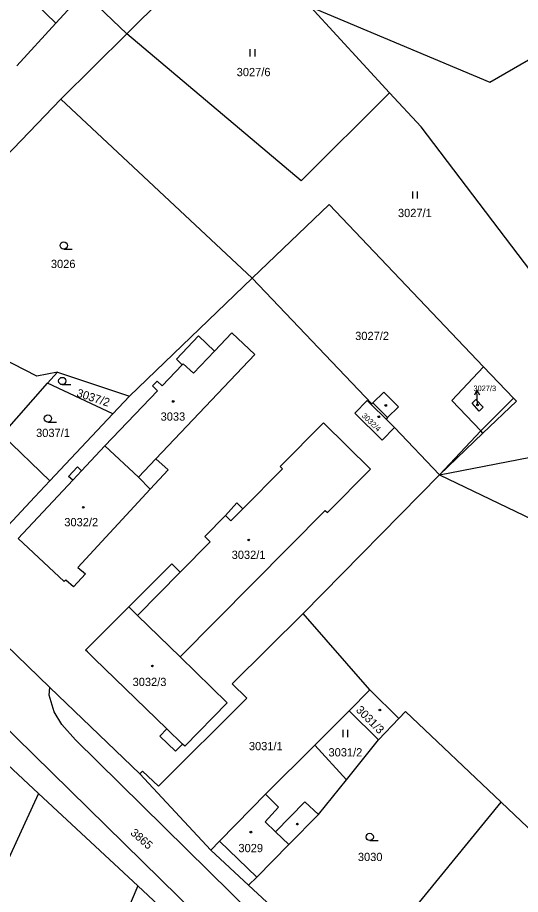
# Model space of a CAD drawing. Extents: x -527335 to -526256, y -1079142 to -1077809.
# Drawn here: x -526577.1 to -526473.7, y -1078894.6 to -1078714.2 of the extents above; entities that cross this region are included whole.
import ezdxf

# ---------------------------------------------------------------- set-up
doc = ezdxf.new("R2010")
doc.units = 0
for name, color, linetype in [('Vrstva 1', 7, 'Continuous'), ('Vrstva 2', 7, 'Continuous'), ('Vrstva 3', 7, 'Continuous'), ('Vrstva 4', 7, 'Continuous'), ('Vrstva 5', 7, 'Continuous'), ('Vrstva 7', 7, 'Continuous')]:
    doc.layers.add(name, color=color, linetype=linetype)

msp = doc.modelspace()

# ---------------------------------------------------------------- linework, layer by layer
at = {"layer": 'Vrstva 1'}
for p, q in [((-526554.68, -1078717.53), (-526539.54, -1078702.51)), ((-526516.89, -1078712.01), (-526500.66, -1078729.66)), ((-526577.27, -1078724.14), (-526569.24, -1078715.32)), ((-526568.24, -1078730.99), (-526554.68, -1078717.53)), ((-526602.93, -1078766.96), (-526568.24, -1078730.99)), ((-526528.93, -1078767.79), (-526568.24, -1078730.99)), ((-526554.11, -1078792.09), (-526528.93, -1078767.79)), ((-526528.93, -1078767.79), (-526504.29, -1078793.67)), ((-526571, -1078789.45), (-526568.95, -1078787.13)), ((-526568.95, -1078787.13), (-526554.11, -1078792.09)), ((-526580.33, -1078800.02), (-526571, -1078789.45)), ((-526557.53, -1078795.73), (-526571, -1078789.45)), ((-526554.11, -1078792.09), (-526557.53, -1078795.73)), ((-526570.48, -1078809.52), (-526557.53, -1078795.73)), ((-526499.66, -1078798.54), (-526490.41, -1078808.25)), ((-526570.48, -1078809.52), (-526580.33, -1078800.02)), ((-526481.45, -1078799.72), (-526490.41, -1078808.25)), ((-526490.41, -1078808.25), (-526446.22, -1078799.76)), ((-526573.56, -1078812.8), (-526570.48, -1078809.52)), ((-526518.39, -1078836.79), (-526490.41, -1078808.25)), ((-526490.41, -1078808.25), (-526410.53, -1078846.68)), ((-526504.69, -1078852.51), (-526518.39, -1078836.79)), ((-526572.83, -1078873.83), (-526599.63, -1078848.92)), ((-526508.94, -1078856.81), (-526504.69, -1078852.51)), ((-526504.69, -1078852.51), (-526498.72, -1078858.41)), ((-526508.94, -1078856.81), (-526516.02, -1078863.88)), ((-526502.9, -1078862.78), (-526508.94, -1078856.81)), ((-526498.72, -1078858.41), (-526502.9, -1078862.78)), ((-526509.51, -1078870.99), (-526502.9, -1078862.78)), ((-526516.02, -1078863.88), (-526526.14, -1078873.99)), ((-526509.51, -1078870.99), (-526516.02, -1078863.88)), ((-526552.02, -1078869.8), (-526537.38, -1078885.46)), ((-526515.27, -1078878.15), (-526509.51, -1078870.99)), ((-526552.41, -1078892.82), (-526572.83, -1078873.83)), ((-526508.07, -1078912.73), (-526477.68, -1078875.63)), ((-526477.68, -1078875.63), (-526463.23, -1078889.43)), ((-526537.38, -1078885.46), (-526529.63, -1078892.67)), ((-526552.41, -1078892.82), (-526555.43, -1078899.96)), ((-526534.91, -1078909.1), (-526552.41, -1078892.82)), ((-526529.63, -1078892.67), (-526508.07, -1078912.73))]:
    msp.add_line(p, q, dxfattribs=at)
for points in [[(-526569.24, -1078715.32), (-526590.17, -1078695.14), (-526598.14, -1078704.26)], [(-526554.68, -1078717.53), (-526563.51, -1078709.03), (-526569.24, -1078715.32)], [(-526516.89, -1078712.01), (-526480.01, -1078727.48), (-526459.29, -1078715.49)], [(-526500.66, -1078729.66), (-526518.84, -1078747.8), (-526554.68, -1078717.53)], [(-526446.22, -1078799.76), (-526494.18, -1078736.71), (-526500.66, -1078729.66)], [(-526528.93, -1078767.79), (-526513.06, -1078752.68), (-526481.31, -1078786.03)], [(-526559.18, -1078802.32), (-526548.37, -1078790.96), (-526549.41, -1078789.97), (-526548.43, -1078788.98), (-526547.41, -1078789.95), (-526543.29, -1078785.62), (-526544.48, -1078784.47), (-526539.92, -1078779.69), (-526536.66, -1078782.81), (-526533.1, -1078779.08), (-526528.38, -1078783.55), (-526548.71, -1078804.96)], [(-526568.95, -1078787.13), (-526573.17, -1078787.97), (-526583, -1078782.94)], [(-526481.45, -1078799.72), (-526481.91, -1078799.24), (-526487.82, -1078793.01), (-526481.31, -1078786.03)], [(-526481.31, -1078786.03), (-526475.18, -1078792.47), (-526474.54, -1078793.14), (-526481.45, -1078799.72)], [(-526504.29, -1078793.67), (-526504.13, -1078793.49), (-526501.86, -1078791.24), (-526498.83, -1078794.3), (-526501.07, -1078796.51), (-526501.37, -1078796.8), (-526499.64, -1078798.52), (-526499.66, -1078798.54)], [(-526499.66, -1078798.54), (-526502.17, -1078801.11), (-526507.83, -1078795.56), (-526505.29, -1078792.97), (-526504.44, -1078793.81), (-526504.29, -1078793.67)], [(-526548.71, -1078804.96), (-526546.18, -1078807.27), (-526549.87, -1078811.21), (-526564.78, -1078827.33), (-526563.18, -1078828.67), (-526565.67, -1078831.32), (-526567.24, -1078829.94), (-526567.55, -1078830.24), (-526577.02, -1078821.35), (-526565.81, -1078809.39), (-526566.65, -1078808.6), (-526564.81, -1078806.64), (-526563.97, -1078807.43), (-526559.18, -1078802.32)], [(-526548.71, -1078804.96), (-526552.31, -1078808.75), (-526559.18, -1078802.32)], [(-526592.15, -1078831.2), (-526590.73, -1078829.68), (-526583.18, -1078822.03), (-526580.48, -1078819.73), (-526580.05, -1078819.71), (-526573.56, -1078812.8)], [(-526592.15, -1078831.2), (-526581.94, -1078841.02), (-526570.51, -1078852.02), (-526552.02, -1078869.8)], [(-526534.07, -1078855.15), (-526542.75, -1078864.11), (-526543.21, -1078863.71), (-526544.66, -1078865.16), (-526547.92, -1078862.03), (-526546.45, -1078860.51), (-526561.4, -1078846.03), (-526562.78, -1078844.67), (-526563.17, -1078844.34), (-526559.27, -1078840.44), (-526554.28, -1078835.46), (-526552.5, -1078837.19), (-526543.73, -1078845.74), (-526534.07, -1078855.15)], [(-526518.39, -1078836.79), (-526533.02, -1078851.25), (-526529.98, -1078854.21), (-526548.16, -1078872.34), (-526551.44, -1078869.24), (-526552.02, -1078869.8)], [(-526477.68, -1078875.63), (-526497.36, -1078856.99), (-526498.72, -1078858.41)], [(-526572.83, -1078873.83), (-526575.65, -1078879.95), (-526588.32, -1078907.48)], [(-526526.14, -1078873.99), (-526529.07, -1078876.91), (-526535.65, -1078883.66), (-526537.38, -1078885.46)], [(-526529.63, -1078892.67), (-526527.96, -1078891.05), (-526521.37, -1078884.35), (-526515.27, -1078878.15)]]:
    msp.add_lwpolyline(points, dxfattribs=at)
at = {"layer": 'Vrstva 3'}
for p, q in [((-526529.3, -1078722.22), (-526529.3, -1078720.72)), ((-526528.3, -1078722.22), (-526528.3, -1078720.72)), ((-526495.88, -1078751.45), (-526495.88, -1078749.95)), ((-526494.88, -1078751.45), (-526494.88, -1078749.95)), ((-526567.65, -1078761.83), (-526565.9, -1078761.83)), ((-526567.95, -1078789.72), (-526566.2, -1078789.72)), ((-526570.9, -1078797.43), (-526569.15, -1078797.43)), ((-526510.22, -1078862.25), (-526510.22, -1078860.75)), ((-526509.22, -1078862.25), (-526509.22, -1078860.75)), ((-526504.73, -1078883.52), (-526502.98, -1078883.52))]:
    msp.add_line(p, q, dxfattribs=at)
for centre in [(-526567.65, -1078761.08), (-526567.95, -1078788.97), (-526570.9, -1078796.68), (-526504.73, -1078882.77)]:
    msp.add_circle(centre, 0.75, dxfattribs=at)
at = {"layer": 'Vrstva 4'}
for p, q in [((-526536.66, -1078782.81), (-526540.99, -1078787.35)), ((-526543.09, -1078785.41), (-526543.29, -1078785.62)), ((-526540.99, -1078787.35), (-526543.09, -1078785.41)), ((-526483.68, -1078793.55), (-526482.89, -1078792.8)), ((-526482.89, -1078792.8), (-526481.39, -1078794.38)), ((-526481.91, -1078799.24), (-526475.18, -1078792.47)), ((-526504.44, -1078793.81), (-526501.37, -1078796.8)), ((-526504.13, -1078793.49), (-526501.07, -1078796.51)), ((-526482.21, -1078795.15), (-526483.68, -1078793.55)), ((-526481.39, -1078794.38), (-526482.21, -1078795.15)), ((-526514.27, -1078797.58), (-526523.14, -1078806.56)), ((-526504.59, -1078807.11), (-526514.27, -1078797.58)), ((-526490.41, -1078808.25), (-526481.91, -1078799.24)), ((-526565.81, -1078809.39), (-526563.97, -1078807.43)), ((-526522.69, -1078807.01), (-526530.82, -1078815.24)), ((-526523.14, -1078806.56), (-526522.69, -1078807.01)), ((-526513.43, -1078816.03), (-526504.59, -1078807.11)), ((-526552.31, -1078808.75), (-526549.87, -1078811.21)), ((-526532.07, -1078814.05), (-526534.4, -1078816.62)), ((-526530.82, -1078815.24), (-526532.07, -1078814.05)), ((-526543.73, -1078845.74), (-526513.87, -1078815.59)), ((-526534.4, -1078816.62), (-526538.64, -1078820.95)), ((-526534.4, -1078816.62), (-526533.28, -1078817.73)), ((-526533.28, -1078817.73), (-526530.82, -1078815.24)), ((-526513.87, -1078815.59), (-526513.43, -1078816.03)), ((-526537.54, -1078822.04), (-526543.7, -1078828.28)), ((-526538.64, -1078820.95), (-526537.54, -1078822.04)), ((-526545.43, -1078826.57), (-526554.28, -1078835.46)), ((-526543.7, -1078828.28), (-526545.43, -1078826.57)), ((-526552.5, -1078837.19), (-526543.7, -1078828.28)), ((-526483.62, -1078954.28), (-526598.1, -1078842.1)), ((-526570.66, -1078853.6), (-526570.51, -1078852.02)), ((-526569.64, -1078857.03), (-526570.66, -1078853.6)), ((-526568.01, -1078859.64), (-526569.64, -1078857.03)), ((-526565.2, -1078862.78), (-526568.01, -1078859.64)), ((-526543.21, -1078863.71), (-526546.45, -1078860.51)), ((-526481.85, -1078944.96), (-526565.2, -1078862.78)), ((-526526.14, -1078873.99), (-526523.47, -1078876.63)), ((-526524.13, -1078881.72), (-526518.08, -1078875.58)), ((-526518.08, -1078875.58), (-526515.27, -1078878.15)), ((-526523.47, -1078876.63), (-526526.25, -1078879.65)), ((-526526.25, -1078879.65), (-526524.13, -1078881.72)), ((-526524.13, -1078881.72), (-526521.37, -1078884.35)), ((-526535.65, -1078883.66), (-526527.96, -1078891.05))]:
    msp.add_line(p, q, dxfattribs=at)
at = {"layer": 'Vrstva 5'}
for centre in [(-526545.14, -1078793.18), (-526501.44, -1078794), (-526482.57, -1078793.89), (-526502.87, -1078796.33), (-526563.63, -1078814.95), (-526529.62, -1078821.67), (-526549.42, -1078847.6), (-526502.65, -1078856.67), (-526519.61, -1078880.14), (-526529.16, -1078881.78)]:
    msp.add_circle(centre, 0.175, dxfattribs=at)
at = {"layer": 'Vrstva 7'}
for p, q in [((-526482.72, -1078790.86), (-526483.17, -1078791.89)), ((-526482.56, -1078793.86), (-526482.72, -1078790.86)), ((-526482.72, -1078790.86), (-526482.17, -1078791.84)), ((-526482.56, -1078793.92), (-526482.56, -1078793.86))]:
    msp.add_line(p, q, dxfattribs=at)

# ---------------------------------------------------------------- texts
at = {"layer": 'Vrstva 2'}
for s, height, p in [('3027/6', 1.7, (-526532.09, -1078726.26)), ('3027/1', 1.7, (-526498.93, -1078755.25)), ('3026', 1.7, (-526570.29, -1078765.73)), ('3027/2', 1.7, (-526507.73, -1078780.54)), ('3027/3', 1.139, (-526483.41, -1078791.05)), ('3033', 1.7, (-526547.73, -1078797.13)), ('3037/1', 1.7, (-526573.33, -1078800.49)), ('3032/2', 1.7, (-526567.53, -1078818.86)), ('3032/1', 1.7, (-526533.12, -1078825.58)), ('3032/3', 1.7, (-526553.49, -1078851.73)), ('3031/1', 1.7, (-526529.58, -1078864.94)), ('3031/2', 1.7, (-526513.21, -1078866.21)), ('3029', 1.7, (-526531.73, -1078885.91)), ('3030', 1.7, (-526507.17, -1078887.73))]:
    msp.add_text(s, height=height, dxfattribs=at).set_placement(p)
for s, height, rotation, p in [('3037/2', 1.7, 342, (-526565.13, -1078792.13)), ('3032/4', 1.14, 316, (-526506.46, -1078796.24)), ('3031/3', 1.7, 315, (-526507.7, -1078856.79)), ('3865', 1.7, 319, (-526554.08, -1078882.14))]:
    msp.add_text(s, height=height, rotation=rotation, dxfattribs=at).set_placement(p)

doc.saveas('drawing.dxf')
